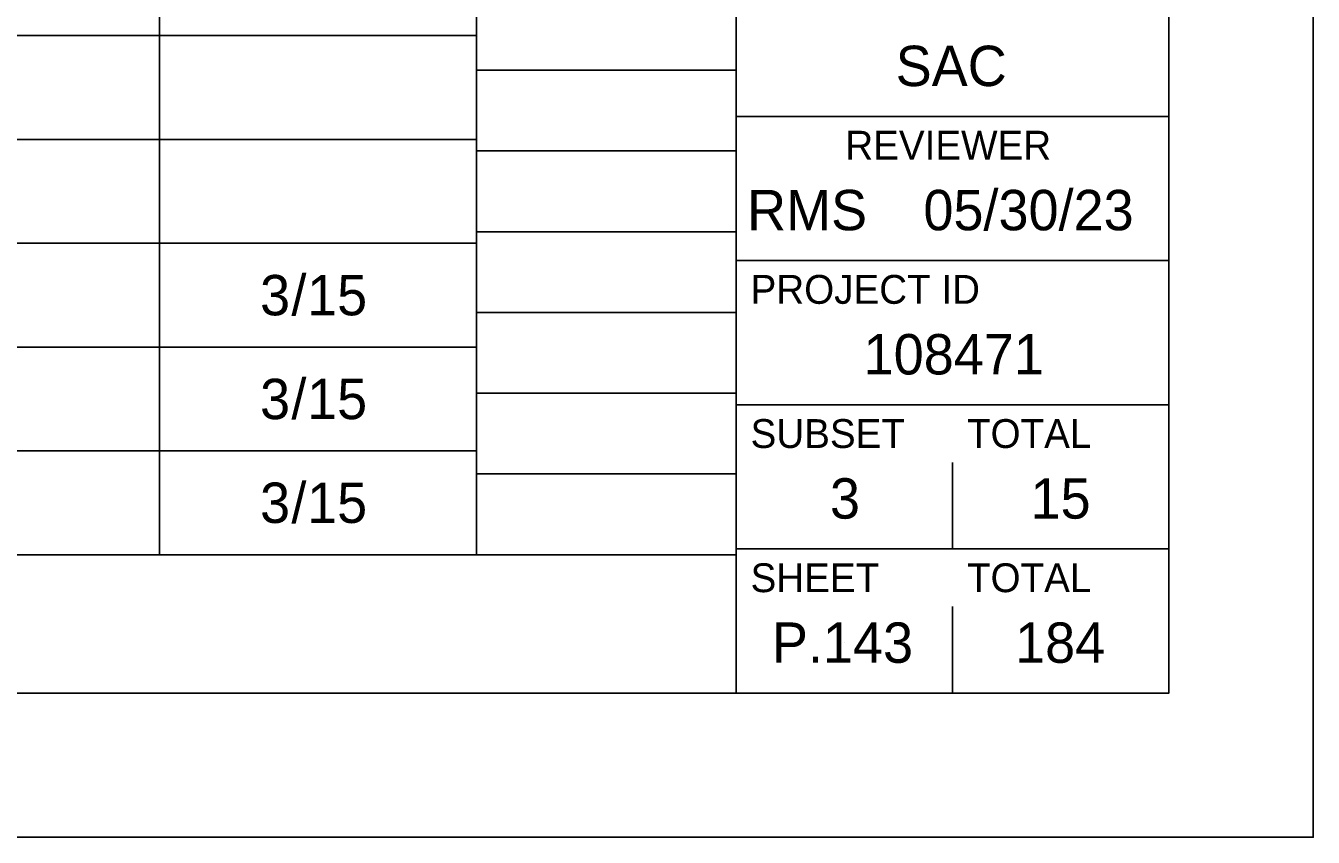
# Model space of a CAD drawing. Extents: x 0 to 34, y 0 to 22.
# Drawn here: x 29.538 to 34, y 0 to 2.814 of the extents above; entities that cross this region are included whole.
import ezdxf

# ---------------------------------------------------------------- set-up
doc = ezdxf.new("R2010")
doc.units = 0
for name, color, linetype in [('SH_Border', 7, 'Continuous'), ('SH_Cut_Line', 7, 'Continuous'), ('SH_Data', 7, 'Continuous'), ('SH_Text', 7, 'Continuous')]:
    doc.layers.add(name, color=color, linetype=linetype)

msp = doc.modelspace()

# ---------------------------------------------------------------- linework, layer by layer
at = {"layer": 'SH_Border'}
for p, q in [((32, 0.5), (32, 21.5)), ((32, 2.5), (33.5, 2.5)), ((32, 2), (33.5, 2)), ((32, 1.5), (33.5, 1.5)), ((32, 1), (33.5, 1))]:
    msp.add_line(p, q, dxfattribs=at)
msp.add_lwpolyline([(1.5, 21.5), (33.5, 21.5), (33.5, 0.5), (1.5, 0.5)], close=True, dxfattribs=at)
at = {"layer": 'SH_Cut_Line'}
msp.add_lwpolyline([(0, 0), (34, 0), (34, 22), (0, 22)], close=True, dxfattribs=at)
at = {"layer": 'SH_Data'}
for p, q in [((31.1, 0.98), (31.1, 21.14)), ((32, 0.98), (32, 21.14)), ((31.1, 2.66), (32, 2.66)), ((31.1, 2.38), (32, 2.38)), ((31.1, 2.1), (32, 2.1)), ((31.1, 1.82), (32, 1.82)), ((31.1, 1.54), (32, 1.54)), ((32.75, 1), (32.75, 1.3)), ((31.1, 1.26), (32, 1.26)), ((31.1, 0.98), (32, 0.98)), ((32.75, 0.5), (32.75, 0.8)), ((32.375, 0.675), (32.375, 0.675))]:
    msp.add_line(p, q, dxfattribs=at)
at = {"layer": 'SH_Text'}
for p, q in [((31.1, 5.66), (31.1, 0.98)), ((30.002, 5.3), (30.002, 0.98)), ((18.968, 2.78), (31.1, 2.78)), ((18.968, 2.42), (31.1, 2.42)), ((18.968, 2.06), (31.1, 2.06)), ((18.968, 1.7), (31.1, 1.7)), ((18.968, 1.34), (31.1, 1.34)), ((18.968, 0.98), (31.1, 0.98))]:
    msp.add_line(p, q, dxfattribs=at)

# ---------------------------------------------------------------- texts
at = {"layer": 'SH_Data'}
for s, height, p in [('SAC', 0.14, (32.5528, 2.605)), ('REVIEWER', 0.1, (32.3783, 2.35)), ('RMS', 0.14, (32.0378, 2.105)), ('05/30/23', 0.14, (32.6489, 2.105)), ('PROJECT ID', 0.1, (32.05, 1.85)), ('108471', 0.14, (32.4418, 1.605)), ('SUBSET', 0.1, (32.05, 1.35)), ('TOTAL', 0.1, (32.8, 1.35)), ('3', 0.14, (32.3251, 1.105)), ('15', 0.14, (33.0202, 1.105)), ('SHEET', 0.1, (32.05, 0.85)), ('TOTAL', 0.1, (32.8, 0.85)), ('P.143', 0.14, (32.1239, 0.605)), ('184', 0.14, (32.9666, 0.605))]:
    msp.add_text(s, height=height, dxfattribs=at).set_placement(p)
at = {"layer": 'SH_Text'}
for s, p in [('3', (30.35, 1.81)), ('/', (30.4587, 1.81)), ('15', (30.513, 1.81)), ('3', (30.35, 1.45)), ('/', (30.4587, 1.45)), ('15', (30.513, 1.45)), ('3', (30.35, 1.09)), ('/', (30.4587, 1.09)), ('15', (30.513, 1.09))]:
    msp.add_text(s, height=0.14, dxfattribs=at).set_placement(p)

doc.saveas('drawing.dxf')
